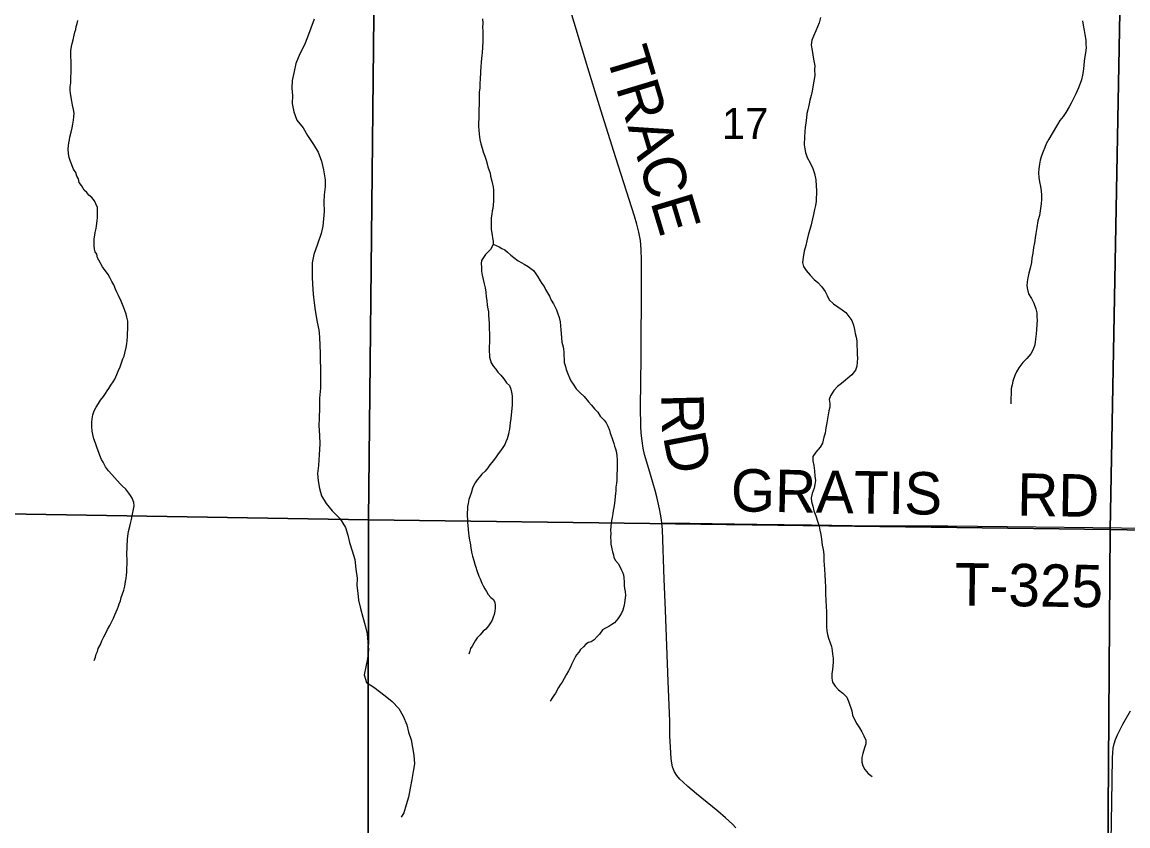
# Model space of a CAD drawing. Extents: x 0 to 34, y 0 to 22.
# Drawn here: x 3.988 to 5.468, y 14.762 to 15.838 of the extents above; entities that cross this region are included whole.
import ezdxf

# ---------------------------------------------------------------- set-up
doc = ezdxf.new("R2010")
doc.units = 0
for name, color, linetype in [('GM_X_Corporation', 7, 'Continuous'), ('GM_X_County_Road', 7, 'Continuous'), ('GM_X_County_Road_Text', 7, 'Continuous'), ('GM_X_Minor_River', 7, 'Continuous'), ('GM_X_Section_Text', 7, 'Continuous'), ('GM_X_State_Route', 7, 'Continuous'), ('GM_X_Township_Road', 7, 'Continuous'), ('GM_X_Township_Road_Text', 7, 'Continuous')]:
    doc.layers.add(name, color=color, linetype=linetype)

msp = doc.modelspace()

# ---------------------------------------------------------------- linework, layer by layer
at = {"layer": 'GM_X_Corporation'}
for points in [[(3.4681, 16.2816), (4.463, 16.2688), (4.4514, 15.172), (3.4532, 15.1884), (3.4534, 15.28)], [(4.463, 16.2688), (5.4651, 16.258), (5.4447, 15.1591), (4.4514, 15.172)], [(5.4651, 16.258), (6.4674, 16.2404), (6.4527, 15.1394), (5.4447, 15.1591)], [(3.4532, 15.1884), (4.4514, 15.172), (4.4501, 14.1693), (3.4483, 14.1786), (3.4477, 14.2699)], [(4.4514, 15.172), (5.4447, 15.1591), (5.4377, 14.1543), (4.4501, 14.1693)], [(5.4447, 15.1591), (6.4527, 15.1394), (6.4438, 14.1407), (5.4377, 14.1543)]]:
    msp.add_lwpolyline(points, close=True, dxfattribs=at)
at = {"layer": 'GM_X_County_Road'}
msp.add_lwpolyline([(4.9434, 14.7597), (4.9388, 14.7648), (4.9295, 14.7732), (4.9194, 14.7821), (4.8907, 14.8052), (4.8793, 14.815), (4.8724, 14.8211), (4.8686, 14.825), (4.8645, 14.8296), (4.8614, 14.8346), (4.8599, 14.8379), (4.8587, 14.8413), (4.8576, 14.8464), (4.8569, 14.8523), (4.8552, 14.883), (4.8549, 14.9024), (4.853, 14.9556), (4.8492, 15.0512), (4.8475, 15.0928), (4.8452, 15.1586), (4.8444, 15.1679), (4.844, 15.1717), (4.8432, 15.1772), (4.8412, 15.187), (4.8376, 15.2028), (4.8354, 15.2112), (4.829, 15.2326), (4.8241, 15.2493), (4.8214, 15.2595), (4.8196, 15.2679), (4.8179, 15.2777), (4.8167, 15.2881), (4.8162, 15.2974), (4.8159, 15.3228), (4.8167, 15.3893), (4.817, 15.4918), (4.817, 15.5198), (4.8167, 15.5341), (4.8157, 15.546), (4.8138, 15.5571), (4.8111, 15.568), (4.8077, 15.5787), (4.7828, 15.6569), (4.765, 15.7132), (4.755, 15.7452), (4.7453, 15.7773), (4.7186, 15.8659)], dxfattribs=at)
at = {"layer": 'GM_X_Minor_River'}
for points in [[(5.057, 15.8444), (5.0549, 15.8373), (5.0528, 15.832), (5.0504, 15.8268), (5.0475, 15.8196), (5.0451, 15.8144), (5.0442, 15.8079), (5.0452, 15.8026), (5.0462, 15.7976), (5.0471, 15.7915), (5.0481, 15.7865), (5.0491, 15.7801), (5.0489, 15.7751), (5.0491, 15.7671), (5.0481, 15.7596), (5.0472, 15.7543), (5.0455, 15.746), (5.0442, 15.7403), (5.0425, 15.7339), (5.0416, 15.729), (5.0398, 15.721), (5.0385, 15.7161), (5.038, 15.7101), (5.0374, 15.7036), (5.0365, 15.6972), (5.036, 15.6919), (5.0354, 15.6847), (5.0351, 15.6741), (5.0357, 15.6687), (5.0367, 15.6637), (5.0391, 15.6572), (5.0431, 15.6499), (5.0467, 15.6426), (5.0488, 15.6357), (5.0504, 15.6273), (5.051, 15.6189), (5.0515, 15.6128), (5.0511, 15.5987), (5.0502, 15.5927)], [(4.0955, 15.511), (4.0904, 15.5195), (4.0886, 15.523), (4.0876, 15.5276), (4.0858, 15.531), (4.0848, 15.5345), (4.0842, 15.5395), (4.0844, 15.5478), (4.0853, 15.5535), (4.0858, 15.5569), (4.0871, 15.5622), (4.0872, 15.5656), (4.0881, 15.5724), (4.0886, 15.5769), (4.0889, 15.5864), (4.0886, 15.5902), (4.0865, 15.5952), (4.0847, 15.5991), (4.081, 15.6038), (4.0773, 15.6069), (4.0744, 15.6104), (4.0707, 15.6136), (4.0671, 15.6197), (4.0642, 15.6236), (4.0632, 15.6286), (4.061, 15.6324), (4.0596, 15.637), (4.0567, 15.6417), (4.0524, 15.6517), (4.0507, 15.6574), (4.0497, 15.662), (4.0495, 15.6689), (4.05, 15.6727), (4.0505, 15.6768), (4.0514, 15.681), (4.0518, 15.6844), (4.0536, 15.6912), (4.0549, 15.6968), (4.0557, 15.7017), (4.0567, 15.707), (4.0572, 15.7116), (4.0573, 15.7165), (4.0567, 15.7215), (4.0553, 15.7272), (4.0543, 15.7326), (4.0533, 15.7375), (4.0524, 15.7433), (4.0521, 15.7471), (4.0522, 15.7516), (4.0528, 15.7573), (4.053, 15.7657), (4.0535, 15.7702), (4.0536, 15.7744), (4.0534, 15.7782), (4.0535, 15.7831), (4.0533, 15.7877), (4.053, 15.7911), (4.0532, 15.7999), (4.0538, 15.8059), (4.055, 15.8097), (4.0559, 15.8146), (4.0576, 15.821), (4.0585, 15.8252), (4.0597, 15.8286), (4.0602, 15.8327), (4.0615, 15.8365), (4.0623, 15.8406)], [(4.3789, 15.8424), (4.3699, 15.8184), (4.3658, 15.8082), (4.3597, 15.7959), (4.3544, 15.7831), (4.3519, 15.7722), (4.3493, 15.7601), (4.349, 15.7502), (4.3498, 15.7403), (4.3495, 15.7293), (4.3515, 15.7183), (4.3557, 15.7071), (4.3642, 15.697), (4.37, 15.6866), (4.378, 15.6746), (4.3841, 15.6642), (4.3887, 15.6523), (4.3915, 15.6408), (4.3937, 15.6274), (4.3935, 15.6179), (4.3924, 15.6073), (4.3918, 15.5975), (4.3922, 15.5849), (4.3905, 15.5652), (4.3883, 15.5554), (4.3834, 15.5411), (4.3784, 15.5272), (4.3762, 15.5163), (4.376, 15.5068), (4.3761, 15.4969), (4.3766, 15.4874), (4.3773, 15.4744), (4.3789, 15.4626), (4.3801, 15.4523), (4.3827, 15.4367), (4.3851, 15.4264), (4.386, 15.4168), (4.3869, 15.3948), (4.387, 15.3853), (4.3871, 15.375), (4.3871, 15.3606), (4.3871, 15.3484), (4.386, 15.3348), (4.386, 15.3219), (4.3856, 15.3082), (4.3849, 15.2984), (4.3861, 15.285), (4.3865, 15.274), (4.3857, 15.2592), (4.3846, 15.2448), (4.3832, 15.2342), (4.384, 15.2243), (4.386, 15.214), (4.3888, 15.2044), (4.3949, 15.194), (4.403, 15.1843), (4.4137, 15.1734), (4.421, 15.1618), (4.4237, 15.1514), (4.4261, 15.1419), (4.4296, 15.1307), (4.4331, 15.1189), (4.4346, 15.1059), (4.4365, 15.0941), (4.4359, 15.0842), (4.4375, 15.0739), (4.4384, 15.0644), (4.4407, 15.0533), (4.4442, 15.0418)], [(4.6042, 15.8428), (4.6045, 15.8371), (4.6043, 15.8314), (4.6046, 15.8268), (4.6048, 15.8227), (4.6047, 15.8192), (4.6045, 15.8124), (4.6043, 15.8048), (4.6037, 15.7972), (4.6032, 15.7938), (4.6031, 15.7896), (4.6026, 15.7847), (4.602, 15.7787), (4.6015, 15.7718), (4.6012, 15.7616), (4.6007, 15.757), (4.6005, 15.7498), (4.5999, 15.7449), (4.5997, 15.7358), (4.5996, 15.7316), (4.5992, 15.7179), (4.5995, 15.7141), (4.599, 15.6986), (4.5993, 15.694), (4.5999, 15.6883), (4.6008, 15.6814), (4.6021, 15.6753), (4.6039, 15.6695), (4.6053, 15.6646), (4.6074, 15.6588), (4.6091, 15.6534), (4.6105, 15.6488), (4.6115, 15.6446)], [(5.4078, 15.8402), (5.4084, 15.8345), (5.4098, 15.8272), (5.4107, 15.8219), (5.412, 15.8142), (5.4123, 15.8093), (5.4125, 15.804), (5.4119, 15.7971), (5.411, 15.7922), (5.4101, 15.7862), (5.4096, 15.7805), (5.4086, 15.7721), (5.4077, 15.7672), (5.4064, 15.7612), (5.4047, 15.7563), (5.4023, 15.7503), (5.3986, 15.7424), (5.3954, 15.7353), (5.3926, 15.73), (5.3898, 15.7252), (5.3854, 15.7173), (5.3818, 15.7121), (5.3775, 15.7069), (5.3743, 15.7013), (5.3671, 15.6893), (5.3627, 15.6815), (5.3592, 15.6755)], [(5.3592, 15.6755), (5.3571, 15.6706), (5.3551, 15.665), (5.3526, 15.6594), (5.351, 15.6537), (5.35, 15.6484), (5.3491, 15.642), (5.3489, 15.6367), (5.3492, 15.6306), (5.3501, 15.6245), (5.3515, 15.6183), (5.3524, 15.6126), (5.353, 15.6069), (5.3529, 15.6012), (5.3523, 15.5951), (5.3509, 15.5857), (5.35, 15.5796), (5.3479, 15.5725), (5.3465, 15.5634), (5.3451, 15.5554), (5.3442, 15.5494), (5.3436, 15.543), (5.3423, 15.5369), (5.3413, 15.5293), (5.34, 15.5225), (5.3395, 15.5165), (5.3374, 15.5089), (5.336, 15.5021), (5.3343, 15.4961), (5.3334, 15.4908), (5.3333, 15.4855), (5.3339, 15.4805), (5.3356, 15.4748), (5.3392, 15.4686), (5.3425, 15.462), (5.3453, 15.4544), (5.3467, 15.449), (5.3465, 15.4441), (5.3468, 15.4391), (5.3466, 15.4342), (5.346, 15.4266), (5.3455, 15.4213), (5.3449, 15.4141), (5.3439, 15.4065), (5.3415, 15.4001), (5.3383, 15.3945), (5.3332, 15.3882), (5.3277, 15.3827), (5.3226, 15.3756), (5.3194, 15.37), (5.317, 15.3651), (5.3145, 15.3576), (5.3136, 15.3527), (5.3123, 15.3478), (5.3117, 15.3273)], [(4.6115, 15.6446), (4.6133, 15.6396), (4.6143, 15.6362), (4.615, 15.6324), (4.6167, 15.6255), (4.6177, 15.6213), (4.6184, 15.6178), (4.619, 15.6136), (4.6188, 15.6083), (4.6191, 15.6034), (4.6189, 15.5988), (4.6184, 15.5939), (4.6179, 15.589), (4.6171, 15.5856), (4.6166, 15.5814), (4.6157, 15.5765), (4.6159, 15.5723), (4.6157, 15.5647), (4.616, 15.5609), (4.6173, 15.5533), (4.6176, 15.5498), (4.6186, 15.5453), (4.6184, 15.5411), (4.6168, 15.5373), (4.6148, 15.534), (4.6113, 15.5306), (4.6082, 15.5273), (4.6054, 15.5232), (4.603, 15.5191), (4.6025, 15.5153), (4.6028, 15.5104), (4.603, 15.505), (4.604, 15.4997), (4.6053, 15.494), (4.6063, 15.4882), (4.6077, 15.4825), (4.6087, 15.4768), (4.6092, 15.4707), (4.6099, 15.4657), (4.6104, 15.4596), (4.6114, 15.4546), (4.6121, 15.4504), (4.6123, 15.4463), (4.6129, 15.4402), (4.6132, 15.4352), (4.6131, 15.4318), (4.6133, 15.4268), (4.6136, 15.4223), (4.6134, 15.4181), (4.6137, 15.4132), (4.6133, 15.4006), (4.6138, 15.39), (4.6158, 15.3823), (4.6191, 15.3773), (4.622, 15.3738), (4.6246, 15.3699), (4.6286, 15.3656), (4.6327, 15.3609), (4.6363, 15.3555), (4.6404, 15.352), (4.6422, 15.347), (4.6432, 15.3428), (4.6438, 15.3382), (4.6441, 15.3344), (4.6438, 15.3257), (4.6437, 15.3215), (4.6422, 15.3079), (4.6413, 15.3018), (4.6403, 15.2935), (4.6394, 15.2901), (4.6389, 15.2867), (4.6372, 15.2806), (4.6356, 15.2765), (4.634, 15.2727), (4.6316, 15.269), (4.6284, 15.2645), (4.6253, 15.2604), (4.6225, 15.2563), (4.619, 15.2515), (4.6142, 15.2459), (4.6115, 15.2418), (4.6076, 15.2374), (4.6033, 15.233), (4.5997, 15.2289), (4.597, 15.2255), (4.5946, 15.2218), (4.5922, 15.2177), (4.591, 15.2143), (4.5889, 15.2079), (4.5876, 15.2041), (4.586, 15.1992), (4.5851, 15.1939), (4.5842, 15.1898), (4.5841, 15.1856), (4.5836, 15.1822), (4.5835, 15.1777), (4.5841, 15.1719), (4.5843, 15.1681), (4.5846, 15.1647), (4.5852, 15.159), (4.5855, 15.1544)], [(5.0502, 15.5927), (5.0489, 15.5874), (5.0476, 15.581), (5.0463, 15.5749), (5.0442, 15.567), (5.0404, 15.5534), (5.0386, 15.5455), (5.0373, 15.5395), (5.0352, 15.5319), (5.0338, 15.5232), (5.0329, 15.5164), (5.0339, 15.5114), (5.0375, 15.506), (5.043, 15.4998), (5.0482, 15.4939), (5.0534, 15.49), (5.0585, 15.4838), (5.0629, 15.4776), (5.0658, 15.4722), (5.0686, 15.4664), (5.0742, 15.4613), (5.0801, 15.4573), (5.0857, 15.453), (5.0909, 15.4498), (5.095, 15.4444), (5.0986, 15.4389), (5.1011, 15.4328), (5.1024, 15.4267), (5.1034, 15.4217), (5.1048, 15.4167), (5.1054, 15.4118), (5.1056, 15.4049), (5.1058, 15.3996), (5.106, 15.3935), (5.1063, 15.3886), (5.1061, 15.3832), (5.1056, 15.3779), (5.1039, 15.3723), (5.0988, 15.3664), (5.0848, 15.3546), (5.0794, 15.3506), (5.0747, 15.345), (5.0703, 15.3379), (5.0683, 15.333), (5.0693, 15.328), (5.0695, 15.3231), (5.0682, 15.3182), (5.0665, 15.3099), (5.0655, 15.3019), (5.0642, 15.2951), (5.0632, 15.2883), (5.0615, 15.2827), (5.0594, 15.2747), (5.0562, 15.2695), (5.0507, 15.2628), (5.0468, 15.2569), (5.0466, 15.2512), (5.0479, 15.2447), (5.0489, 15.2378), (5.0494, 15.2306), (5.05, 15.2249), (5.0491, 15.2192), (5.0482, 15.2143), (5.0457, 15.2071), (5.0444, 15.2015), (5.0447, 15.1965), (5.0468, 15.1904), (5.0481, 15.1839), (5.0506, 15.1773), (5.0534, 15.1689), (5.0551, 15.1635), (5.0561, 15.1582), (5.0574, 15.1524), (5.0584, 15.1463), (5.0593, 15.1383), (5.0603, 15.1322), (5.0612, 15.1257), (5.0614, 15.117), (5.0616, 15.1117), (5.0622, 15.1056), (5.0627, 15.0983), (5.0629, 15.09), (5.0634, 15.082), (5.0637, 15.077), (5.0635, 15.0721), (5.0641, 15.0649), (5.0645, 15.055), (5.0648, 15.0496), (5.0649, 15.0413), (5.0647, 15.0344), (5.0649, 15.0287), (5.0655, 15.0234), (5.0662, 15.0184), (5.0675, 15.0135), (5.07, 15.0073), (5.0718, 15.0023), (5.0724, 14.997), (5.073, 14.992), (5.0736, 14.9867), (5.0739, 14.9817), (5.0733, 14.9768)], [(4.6184, 15.5411), (4.6267, 15.5374), (4.6301, 15.5354), (4.6342, 15.5334), (4.6379, 15.5303), (4.6423, 15.5263), (4.646, 15.5232), (4.652, 15.5189), (4.6568, 15.5161), (4.6602, 15.5144), (4.6654, 15.5113), (4.6688, 15.5085), (4.6725, 15.5057), (4.6758, 15.5015), (4.6783, 15.4972), (4.6816, 15.4922), (4.6837, 15.4887), (4.6867, 15.4844), (4.6888, 15.4806), (4.6939, 15.4713), (4.696, 15.4663), (4.6993, 15.4613), (4.7014, 15.4567), (4.7032, 15.4532), (4.7046, 15.4493), (4.7071, 15.4428), (4.7081, 15.4371), (4.7093, 15.4264), (4.7095, 15.4215), (4.7107, 15.41), (4.7121, 15.4039), (4.7127, 15.4005), (4.713, 15.397), (4.7132, 15.391), (4.7135, 15.3875), (4.7137, 15.3826), (4.7155, 15.3772), (4.7161, 15.3734), (4.7183, 15.3676), (4.7208, 15.3622), (4.7225, 15.358), (4.7255, 15.3538), (4.7298, 15.3475), (4.735, 15.3421), (4.7405, 15.337), (4.7464, 15.33), (4.7501, 15.3257), (4.7541, 15.3206), (4.7585, 15.316), (4.7618, 15.3109), (4.767, 15.3055), (4.7699, 15.302), (4.772, 15.2973), (4.7742, 15.292), (4.7752, 15.2881), (4.7773, 15.2824), (4.7787, 15.2785), (4.7801, 15.2743), (4.7811, 15.2705), (4.7822, 15.267), (4.7836, 15.262), (4.7842, 15.2571), (4.7848, 15.2529), (4.7846, 15.2442), (4.7848, 15.2388), (4.7843, 15.2331), (4.784, 15.2252), (4.7835, 15.221), (4.783, 15.2157), (4.7829, 15.2111), (4.7824, 15.2074), (4.7819, 15.2032), (4.7814, 15.1986), (4.7809, 15.1945), (4.78, 15.1884), (4.7791, 15.1847), (4.7786, 15.1805), (4.7777, 15.1752), (4.7772, 15.171), (4.7762, 15.1635), (4.7757, 15.1578), (4.7759, 15.1543), (4.7758, 15.1483), (4.776, 15.1441), (4.7763, 15.1395), (4.7769, 15.1353), (4.7783, 15.1292), (4.7797, 15.125), (4.7803, 15.1215), (4.7825, 15.1177), (4.7858, 15.1138), (4.788, 15.1095), (4.7901, 15.1057), (4.7919, 15.1022), (4.793, 15.0984), (4.7936, 15.0946), (4.7938, 15.0892), (4.7941, 15.0843), (4.7943, 15.0801), (4.7954, 15.0763), (4.7956, 15.0706)], [(4.0843, 14.9839), (4.086, 14.988), (4.0868, 14.9922), (4.0885, 14.9959), (4.0897, 14.9997), (4.0925, 15.0053), (4.0946, 15.0102), (4.097, 15.0155), (4.0998, 15.0203), (4.1022, 15.0252), (4.1054, 15.0308), (4.1102, 15.0406), (4.1118, 15.0447), (4.1139, 15.0488), (4.1155, 15.0529), (4.1167, 15.0563), (4.1176, 15.0597), (4.1196, 15.0638), (4.1205, 15.068), (4.1238, 15.0778), (4.1255, 15.0831), (4.1264, 15.0895), (4.1273, 15.0933), (4.1274, 15.0978), (4.1279, 15.102), (4.1284, 15.1187), (4.1282, 15.1255), (4.1288, 15.146), (4.1293, 15.1502), (4.1302, 15.1563), (4.1319, 15.1631), (4.1328, 15.1672), (4.1344, 15.1725), (4.1353, 15.1774), (4.1371, 15.1865), (4.1376, 15.191), (4.1374, 15.1952), (4.1353, 15.201), (4.1327, 15.2045), (4.1305, 15.2079), (4.1265, 15.213), (4.1224, 15.2173), (4.1191, 15.2204), (4.1114, 15.2286), (4.1081, 15.2329), (4.1033, 15.2376), (4.0996, 15.243), (4.0964, 15.2492), (4.0942, 15.253), (4.0917, 15.258), (4.0907, 15.2623), (4.0882, 15.268), (4.0861, 15.2745), (4.0836, 15.2807), (4.0823, 15.2861), (4.0816, 15.2906), (4.0811, 15.2971), (4.0809, 15.3028), (4.0814, 15.3074), (4.0826, 15.3126), (4.0843, 15.3179), (4.0871, 15.3228), (4.0899, 15.328), (4.0927, 15.3321), (4.0966, 15.337), (4.0994, 15.3414), (4.1018, 15.3448), (4.1038, 15.3481), (4.1065, 15.3523), (4.1097, 15.3567), (4.1117, 15.3605), (4.1145, 15.3668), (4.1166, 15.3713), (4.119, 15.377), (4.1207, 15.3823), (4.1227, 15.3875), (4.1243, 15.3913), (4.1252, 15.3954), (4.1269, 15.403), (4.1278, 15.4079), (4.1283, 15.4121), (4.1289, 15.417), (4.129, 15.4223), (4.1295, 15.4265), (4.1292, 15.4303), (4.1293, 15.4341), (4.1291, 15.4379), (4.1281, 15.4432), (4.1271, 15.4474), (4.1253, 15.4524), (4.1239, 15.4559), (4.1221, 15.4605), (4.1204, 15.4647), (4.1168, 15.4724), (4.115, 15.4759), (4.1128, 15.4809), (4.1104, 15.4867), (4.1078, 15.4913), (4.1053, 15.4963), (4.1032, 15.5005), (4.0955, 15.511)], [(4.5855, 15.1544), (4.5861, 15.1506), (4.5867, 15.1449), (4.5877, 15.1411), (4.5887, 15.1346), (4.5897, 15.1288), (4.591, 15.1235), (4.5928, 15.1177), (4.5938, 15.1128), (4.5952, 15.1089), (4.5966, 15.1043), (4.5994, 15.0966), (4.6012, 15.0932), (4.6033, 15.0874), (4.6051, 15.0839), (4.6073, 15.0797), (4.6098, 15.0762), (4.612, 15.0723), (4.6153, 15.0681), (4.619, 15.0653), (4.6208, 15.0615), (4.6211, 15.058), (4.6213, 15.0542), (4.6208, 15.0497), (4.6199, 15.0455), (4.6187, 15.0418), (4.6171, 15.0376), (4.6151, 15.0343), (4.6123, 15.0302), (4.6088, 15.0257), (4.6053, 15.0228), (4.6013, 15.0179), (4.597, 15.0139), (4.5943, 15.0101), (4.5927, 15.0068), (4.5903, 15.003), (4.5883, 14.9997), (4.5871, 14.9963), (4.5858, 14.9921)], [(4.7956, 15.0706), (4.795, 15.0645), (4.7942, 15.0607), (4.7937, 15.0562), (4.792, 15.0509), (4.7904, 15.0472), (4.788, 15.0434), (4.7856, 15.0393), (4.7809, 15.0341), (4.7774, 15.0319), (4.7732, 15.0294), (4.7689, 15.0272), (4.7651, 15.0247), (4.7607, 15.0191), (4.7576, 15.0158), (4.7537, 15.0113), (4.7498, 15.0088), (4.7464, 15.0077), (4.7425, 15.0056), (4.7394, 15.0019), (4.7355, 14.9985), (4.7331, 14.9948), (4.73, 14.9915), (4.7284, 14.9881), (4.7255, 14.9829), (4.7235, 14.9784), (4.7219, 14.9746), (4.7195, 14.9701), (4.7163, 14.9645), (4.7135, 14.9596), (4.7111, 14.9548), (4.7083, 14.9511), (4.706, 14.9477), (4.702, 14.9402), (4.6996, 14.9369), (4.6972, 14.9328), (4.6948, 14.9294)], [(4.4442, 15.0418), (4.4473, 15.0304), (4.4496, 15.0196), (4.4508, 15.0082), (4.4517, 14.9979), (4.4502, 14.9858), (4.4458, 14.9647), (4.4489, 14.9543), (4.4586, 14.948), (4.4739, 14.9365), (4.4835, 14.929), (4.4924, 14.9193), (4.4982, 14.9093), (4.5028, 14.8974), (4.5051, 14.8878), (4.5087, 14.8774), (4.5106, 14.8671), (4.5123, 14.8568), (4.5131, 14.8454), (4.5116, 14.8352), (4.5098, 14.8246), (4.5076, 14.8129), (4.505, 14.8008), (4.5021, 14.7906), (4.4987, 14.7797), (4.4955, 14.7741)], [(5.0733, 14.9768), (5.0728, 14.9715), (5.0719, 14.9658), (5.0721, 14.9601), (5.0731, 14.9548), (5.0763, 14.9494), (5.0808, 14.9443), (5.0867, 14.94), (5.0919, 14.9345), (5.0947, 14.9279), (5.0989, 14.9164), (5.0999, 14.9107), (5.1028, 14.9038), (5.1056, 14.8988), (5.1089, 14.8937), (5.1122, 14.8883), (5.1151, 14.8829), (5.1176, 14.8771), (5.1174, 14.8722), (5.1157, 14.8669), (5.1136, 14.859), (5.1123, 14.8537), (5.1122, 14.8477), (5.1135, 14.8427), (5.1161, 14.8377), (5.1208, 14.8326), (5.126, 14.8286)]]:
    msp.add_lwpolyline(points, dxfattribs=at)
at = {"layer": 'GM_X_State_Route'}
msp.add_lwpolyline([(5.4398, 14.1599), (5.4419, 14.3392), (5.4431, 14.4541), (5.4432, 14.4685), (5.4445, 14.6044), (5.4451, 14.6665), (5.4461, 14.7423), (5.4468, 14.7938), (5.4477, 14.8534), (5.4481, 14.8602), (5.4488, 14.8662), (5.45, 14.8721), (5.4519, 14.8781), (5.4544, 14.8841), (5.4571, 14.8895), (5.4619, 14.8983), (5.4719, 14.9162)], dxfattribs=at)
at = {"layer": 'GM_X_Township_Road'}
msp.add_lwpolyline([(4.8444, 15.1679), (4.8817, 15.1677), (4.9717, 15.1661), (5.045, 15.1653), (5.1263, 15.1642), (5.1697, 15.164), (5.2275, 15.164), (5.307, 15.1633), (5.4598, 15.1613), (5.5453, 15.1598), (5.5993, 15.1587), (5.6061, 15.1583), (5.6121, 15.158)], dxfattribs=at)

# ---------------------------------------------------------------- texts
at = {"layer": 'GM_X_County_Road_Text'}
for s, height, rotation, p in [('TRACE', 0.05682, 286.7795, (4.769, 15.7959)), ('R', 0.0568, 271.4111, (4.8435, 15.3408)), ('D', 0.0568, 281.124, (4.8458, 15.2839))]:
    msp.add_text(s, height=height, rotation=rotation, dxfattribs=at).set_placement(p)
at = {"layer": 'GM_X_Section_Text'}
msp.add_text('17', height=0.04186, rotation=0, dxfattribs=at).set_placement((4.9249, 15.6818))
at = {"layer": 'GM_X_Township_Road_Text'}
for s, rotation, p in [('GRATIS', 359.0485, (4.9365, 15.1835)), ('RD', 359.0128, (5.3199, 15.1777)), ('T-325', 359.1574, (5.2364, 15.0576))]:
    msp.add_text(s, height=0.05682, rotation=rotation, dxfattribs=at).set_placement(p)

doc.saveas('drawing.dxf')
